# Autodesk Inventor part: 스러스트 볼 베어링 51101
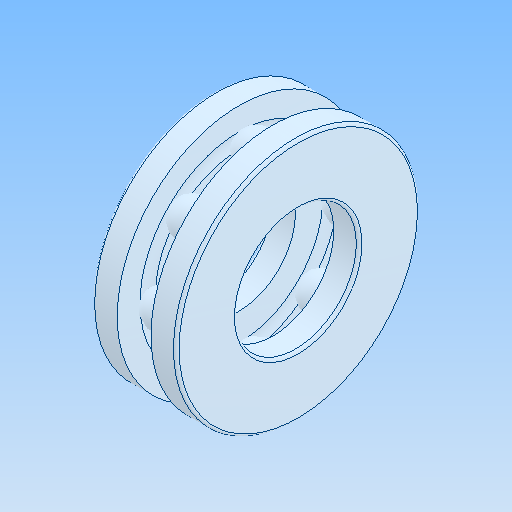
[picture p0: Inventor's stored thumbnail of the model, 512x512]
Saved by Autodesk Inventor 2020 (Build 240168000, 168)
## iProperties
Created: 2024-07
Part Number: 스러스트 볼 베어링 51101
Material: 강철, 연강
Description: 롤링 베어링 - 플랫 뒷면이 있는 스러스트 볼 베어링
Document SubType Name: Modeling
Designer: oem
Density: 7.85 g/cm^3
Appearance: 기본값
Author: jhkim
Sending System: Autodesk Inventor 2025
Preprocessor: ST-DEVELOPER v20
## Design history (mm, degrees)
feature "Solid1"
feature "Solid1:1"
feature "Solid1:2"
feature "Solid1:3"
feature "Solid1:4"
feature "Solid1:5"
feature "Solid1:6"
feature "Solid1:7"
feature "Solid1:8"
feature "Solid1:9"
node "솔리드1"
node "솔리드2"
node "솔리드3"
node "솔리드4"
node "솔리드5"
node "솔리드6"
node "솔리드7"
node "솔리드8"
node "솔리드9"
node "솔리드10"
